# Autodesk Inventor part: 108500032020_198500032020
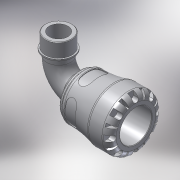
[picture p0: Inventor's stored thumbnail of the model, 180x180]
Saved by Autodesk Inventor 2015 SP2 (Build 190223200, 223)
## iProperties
Created: 2016-12
Part Number: 108500032020_198500032020
Material: PVC-Piping
Description: PLASSON 90° ELBOW WITH THREADED MALE OFFTAKE 32X2'' SERIES 1
Document SubType Name: Modeling
Designer: KIM
Mass: 211.794 g
Surface Area: 487.643 cm^2
Volume: 151.282 cm^3
Density: 1.4 g/cm^3
Appearance: Smooth - White
Author: KIM
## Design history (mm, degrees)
derived "1085.ipt"
feature "Solid1::1085.ipt"
tag "TaggingFeature1"
body "Solid1"
other parameters: "d1" = 22.26, "d2" = 32, "d4" = 58, "d8" = 55.1, "d13" = 7.2, "d14" = 7.2, "d15" = 0, "d17" = 360 deg, "d19" = 8 deg, "d20" = 0.64, "d21" = 0.64, "d22" = 8 deg, "d24" = 0, "d26" = 360 deg, "d33" = 5.8, "d43" = 49.3, "d51" = 0.58, "d54" = 11.2, "d55" = 7.04, "d57" = 14.112, "d58" = 0, "d74" = 0, "d78" = 53, "d82" = 0.64, "d115" = 360 deg, "d207" = 90 deg, "d228" = 9.52, "d247" = 1.16, "d248" = 2.5, "d268" = 30.305, "d269" = 2.5, "d270" = 89, "d276" = 59.614, "d277" = 25, "d278" = 65.5754, "d279" = 66, "d280" = 27.5, "d281" = 8.9421, "d283" = 44.7105, "d286" = 0, "d287" = 0, "d288" = 25, "d290" = -4.2063, "d292" = 30 deg, "d_" = 32, "E_" = 58, "l_" = 53, "A_" = 89, "A_1" = 66, "l_2" = 25, "R_" = 59.614, "d9" = 9, "d11" = 58, "d289" = 41.7298
